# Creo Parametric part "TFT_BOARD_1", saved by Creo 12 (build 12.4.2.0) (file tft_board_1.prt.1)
Units: Custom; MM, KILOGRAM, SECS

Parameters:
  PTC_WM_ITERATION = "0"
  PTC_WM_VERSION = "-.0"
  PTC_WM_LIFECYCLE_STATE = "In Work"
  PTC_WM_LIFECYCLE = "MO_CADDocument"
  PTC_WM_CREATED_BY = "Maximilian Roepper (Z0017RMS: MO)"
  PTC_WM_CREATED_ON = "18-Sep-26 11:36:42 AM"
  PTC_WM_MODIFIED_BY = "Maximilian Roepper (Z0017RMS: MO)"
  PTC_WM_MODIFIED_ON = "18-Sep-26 11:36:46 AM"
  PDMLINKNUMBER = "PDM000071455182"
  PTC_WM_NAME = "tft_board_1.prt"
  PTC_WM_NUMBER = "PDM000071455182"

Other parameters: WEIGHT, WEIGHT_FACTOR, WEIGHT_ADD, _MASS_TEMP, _DIFF_TEMP, MC_ERRORS, SUPPLIER

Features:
  1. coordinate system
  2. datum plane "PRT_YZ"
  3. datum plane "PRT_XY"
  4. datum plane "PRT_XZ"
  5. coordinate system
  6. datum axis
  7. datum axis
  8. datum axis
  9. coordinate system
  10. imported feature

Other named items: PRT, SIEMENS_MO, DRW_VIEW_ORG, PRT_X, PRT_Y, PRT_Z, CS0, ROUGH_GROB

Layers: 00_STD_CSYS-KSYS, 01_STD_PLANES-EBENEN, 02_STD_AXES-ACHSEN, 03_STD_CSYS-KSYS, 24_IMPORT_FEAT-IMPORT_KE

Surfaces: 11 plane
